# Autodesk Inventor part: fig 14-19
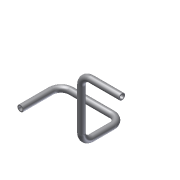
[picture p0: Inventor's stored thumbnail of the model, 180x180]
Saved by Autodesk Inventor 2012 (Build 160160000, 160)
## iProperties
Created: 2005-03
Part Number: fig 14-19
Document SubType Name: Modeling
Designer: CADCIM
Manufacturer: Standard
Standards Organization: Custom
Density: 1 g/cm^3
Material: Default
Author: CADCIM
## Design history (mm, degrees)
sketch "Sketch1"
  geometry: L1 (-32.875, 0)-(-32.875, 40); L2 (-32.875, 40)-(27.125, 40); L3 (27.125, 40)-(27.125, 0); 1 further point
  constraints: 6 end point, 1 horizontal alignment, 1 parallel, 1 perpendicular, 1 vertical, 1 other
  dimensions: "d0" = 40 distance of L1.start L1.end; "d1" = 60 distance of L1.end L2.end; "d2" = 40 distance of L2.end L3.end
workplane "Work Plane1"
sketch "Sketch2"
  geometry: L1 (0, 0)-(0, 60); L2 (0, 60)-(40, 60)
  constraints: 4 end point, 1 perpendicular, 1 vertical
  dimensions: "d3" = 60 distance of L1.start L1.end; "d4" = 40 distance of L1.end L2.end
sketch "3D Sketch1" dims "d5" = 10, "d6" = 10 (= d5)
  geometry: L1 through (10, 10) direction (-1, -2.22e-16); L2 through (0, 50) direction (-2.22e-16, 1); 18 other entities
  constraints: 2 horizontal, 2 vertical
  dimensions: "d7" = 10 distance of the line from the sketch origin of L1 (= d5); "d8" = 10 dimension on L2 (= d5)
workplane "Work Plane2"
sketch "Sketch3"
  geometry: C1 r 3 at (0, 0); C2 r 2 at (0, 0)
  constraints: 2 centre point, 1 coincident
  dimensions: "d9" = 6 diameter of C1; "d10" = 4 diameter of C2
sweep "Sweep1" sketch "Sketch3" dims "d11" = 0
body "Solid1"
